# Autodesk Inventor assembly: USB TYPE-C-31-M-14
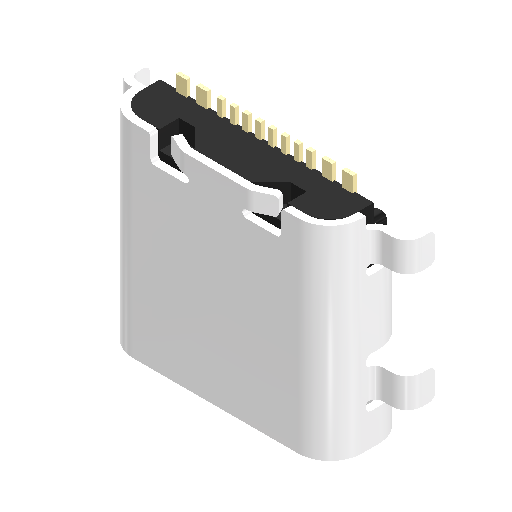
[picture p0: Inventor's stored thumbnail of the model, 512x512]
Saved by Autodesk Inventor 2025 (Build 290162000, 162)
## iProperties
Created: 2025-05
Part Number: USB TYPE-C-31-M-14
Document SubType Name: Assembly
Designer: R5800u
Author: R5800u
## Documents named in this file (3)
- C:\Users\R5800u\Desktop\drone\c3\beetle ESP32-C3\USB TYPE-C-31-M-14 v1.iam
- C:\Users\R5800u\Desktop\drone\c3\beetle ESP32-C3\Shroud.ipt
- C:\Users\R5800u\Desktop\drone\c3\beetle ESP32-C3\Plastic Body & Connector.ipt
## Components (2 placed, 2 different names)
1. Shroud:1
2. Plastic Body & Connector:1
